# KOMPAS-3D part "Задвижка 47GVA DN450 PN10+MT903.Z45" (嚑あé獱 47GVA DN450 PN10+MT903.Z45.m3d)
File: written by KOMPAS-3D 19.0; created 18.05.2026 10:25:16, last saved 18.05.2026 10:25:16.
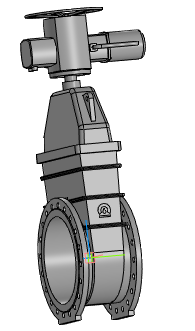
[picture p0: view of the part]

Document properties: Автор: Энергия; Полное имя файла: ..\Задвижка 47GVA DN50_DN1000+MT903.Z\Задвижка 47GVA DN450 PN10+MT903.Z45.a3d

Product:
- Part/product: Задвижка 47GVA DN450 PN10+MT903.Z45
    Масса: 846.48
  - Body: Электропривод MT903.Z45-60
      Масса: 170.293
  - Body: Задвижка 47GVA DN450 PN10 без исполнительного механизма
      Масса: 676.188

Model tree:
1. Операция без истории:1
2. Операция без истории:2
